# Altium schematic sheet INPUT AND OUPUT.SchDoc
size A
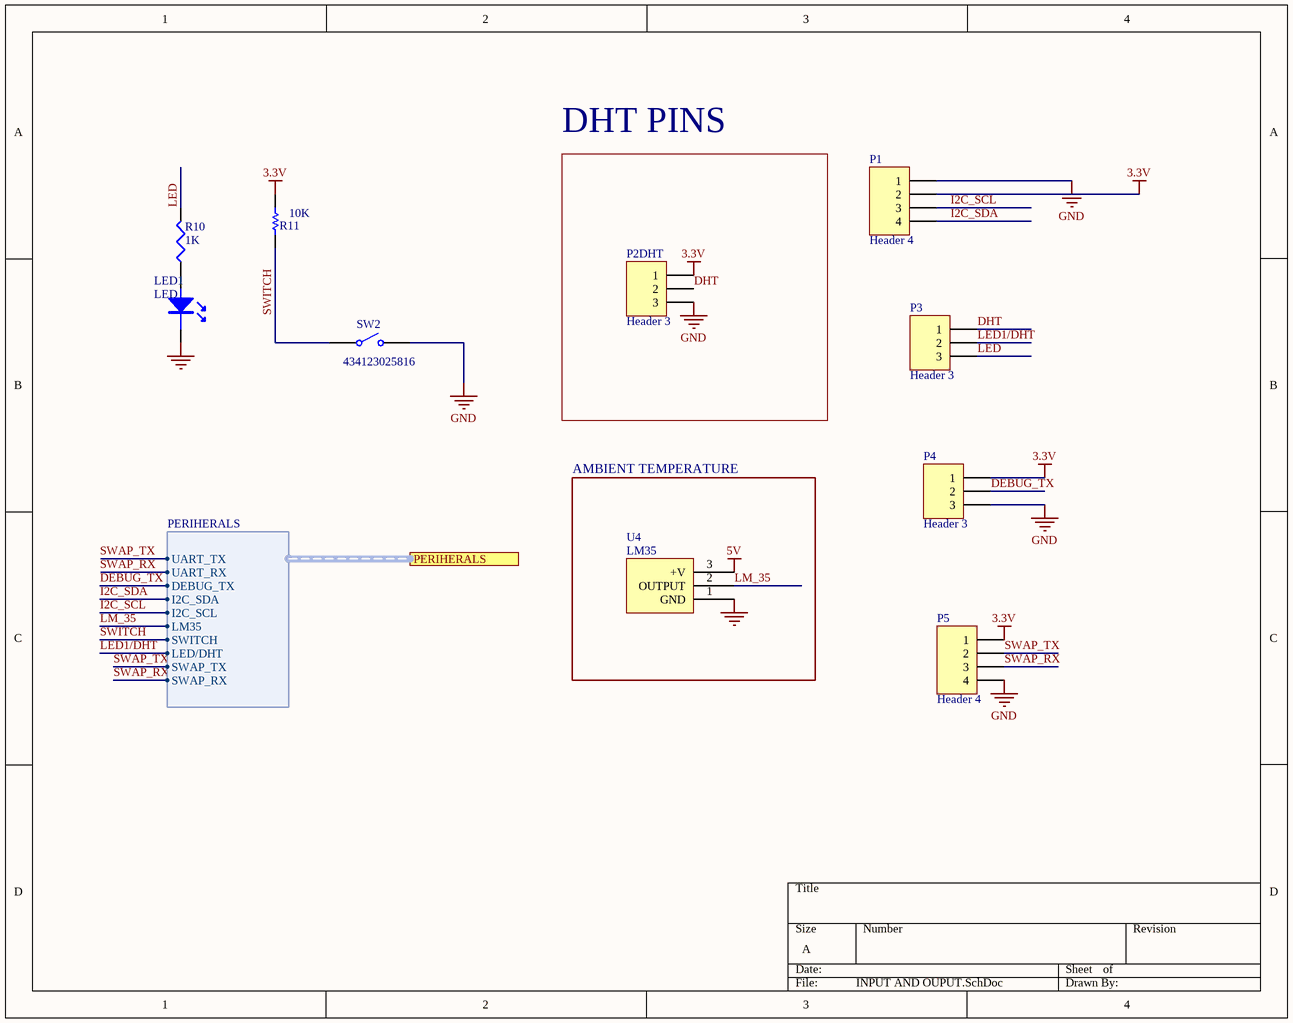
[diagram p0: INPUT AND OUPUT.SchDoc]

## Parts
LED1  LED  [Type 3mm]
P1  Header 4  [HDR1X4]
P2DHT  Header 3  [HDR1X3]
P3  Header 3  [HDR1X3]
P4  Header 3  [HDR1X3]
P5  Header 4  [HDR1X4]
R10  1K  [RESC0603]
R11  10K  [RESC0603]
SW2  434123025816  [434123025816]
U4  LM35  [TO92S]

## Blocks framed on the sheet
DHT PINS: P2DHT
AMBIENT TEMPERATURE: U4

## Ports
PERIHERALS (harness PERIHERALS)

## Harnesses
PERIHERALS: UART_TX, UART_RX, DEBUG_TX, I2C_SDA, I2C_SCL, LM35, SWITCH, LED/DHT, SWAP_TX, SWAP_RX

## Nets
3.3V: P1.2 P2DHT.1 P4.1 P5.1 R11.2
5V: U4.3(+V)
GND: LED1.1(A) P1.1 P2DHT.3 P4.3 P5.4 SW2.2 U4.1(GND)
DEBUG_TX: P4.2 ; port PERIHERALS.DEBUG_TX
DHT: P2DHT.2 P3.1
I2C_SCL: P1.3 ; port PERIHERALS.I2C_SCL
I2C_SDA: P1.4 ; port PERIHERALS.I2C_SDA
LED: P3.3 R10.2
LED1/DHT: P3.2 ; port PERIHERALS.LED/DHT
LM_35: U4.2(OUTPUT) ; port PERIHERALS.LM35
SWAP_RX: P5.3 ; port PERIHERALS.SWAP_RX
SWAP_TX: P5.2 ; port PERIHERALS.SWAP_TX
SWITCH: R11.1 SW2.1 ; port PERIHERALS.SWITCH
NetLED1_2: LED1.2(K) R10.1

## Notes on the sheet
- Labels drawn without touching a wire or pin: SWAP_RX, SWAP_TX

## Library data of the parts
P1 P5 = Header 4: Header, 4-Pin
P2DHT P3 P4 = Header 3: Header, 3-Pin
R10 = RES1: RESISTOR
R11 = CMP-1013-00215-1: 2R55 0.125W 1% 0805 (2012 Metric)  SMD; Case-Metric: 2012; Value: 2.55 Ohm; Case-EIA: 0805
SW2 = CMP-1460-00004-1: WS-TASV J-Bend SMD Tact Switch 6.0X3.8 mm; Manufacturer: Wuerth Elektronik; NoPins: 02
